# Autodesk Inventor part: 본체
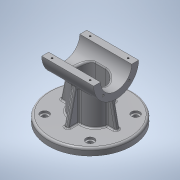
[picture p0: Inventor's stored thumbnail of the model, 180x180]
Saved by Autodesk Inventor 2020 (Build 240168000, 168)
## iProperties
Created: 2015-12
Part Number: 본체
Material: 알루미늄 6061
Document SubType Name: Modeling
Designer: mduedu
Density: 2.71 g/cm^3
Appearance: 알루미늄 - 평지
Mass: 544.569 g
Surface Area: 542.441 cm^2
Volume: 200.948 cm^3
Author: mduedu
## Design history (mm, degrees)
sketch "스케치1"
  geometry: L1 (45, 40)-(-45, 40); L2 (-45, 40)-(-45, -40); L3 (-45, -40)-(45, -40); L4 (45, -40)-(45, 40); L5 (45, 40)-(-45, -40); L6 (-45, 40)-(45, -40); 2 further points
  constraints: 12 end point, 2 midpoint, 2 parallel, 1 coincident, 1 horizontal, 1 perpendicular, 3 other
  dimensions: "d0" = 90 distance of L2.end L3.end; "d2" = 80 distance of L1.end L2.end
extrude "돌출1" new body sketch "스케치1" distance "d3" = 10; taper "d4" = 0 deg
sketch "스케치2"
  geometry: C1 r 32.5 at (80, 0); 1 further point
  constraints: 1 centre point
  dimensions: "d5" = 65 diameter of C1; "d116" = 80 distance of point (0, 0) C1.centre
extrude "돌출2" join sketch "스케치2" stored distance "d7" = 75; taper "d8" = 0 deg
sketch "스케치3"
  geometry: L1 (-27.5, -20)-(27.5, -20); L2 (27.5, -20)-(27.5, 20); L3 (27.5, 20)-(-27.5, 20); L4 (-27.5, 20)-(-27.5, -20); L5 (-27.5, -20)-(27.5, 20); L6 (27.5, -20)-(-27.5, 20); 1 further point
  constraints: 12 end point, 2 midpoint, 2 parallel, 1 horizontal, 1 perpendicular
  dimensions: "d9" = 55 distance of L2.end L3.end; "d11" = 40 distance of L1.end L2.end
extrude "돌출3" new body sketch "스케치3" stored distance "d12" = 75; taper "d13" = 0 deg
fillet "모깎기1"
fillet "모깎기2"
feature "결합1"
  node "솔리드2"
sketch "스케치4"
  geometry: L1 (-37.5, 47.5)-(37.5, 47.5) reference; L2 (32.5, 47.5)-(40.208, 10); L3 (37.5, 47.5)-(37.5, 112.5) reference; L4 (60.208, 0)-(60.208, 10) reference; L5 (60.208, 10)-(-60.208, 10) reference; 1 further point
  constraints: 2 end point, 2 point on line
  dimensions: "d15" = 5 distance from line of L2.start L3; "d117" = 20 distance from line of L2.end L4
sketch "스케치5"
  geometry: L1 (10, 35.208)-(58.179, 24.085); L2 (0, 60.208)-(10, 60.208) reference; L3 (10, -60.208)-(10, 60.208) reference; 2 further points
  constraints: 2 end point, 1 point on line, 2 other
  dimensions: "d118" = 25 distance from line of L1.start L2; "d119" = 77 deg angle of L1 L3
feature "리브1" dims "d19" = 1, "d20" = 6, "d21" = 0, "d22" = 0, "d23" = 1, "d24" = 1
feature "리브2" dims "d25" = 1, "d26" = 6, "d27" = 0, "d28" = 0, "d29" = 1, "d30" = 1
fillet "모깎기4" dims "d31" = 2
fillet "모깎기5" dims "d32" = 2
fillet "모깎기16" dims "d149" = 2
sketch "스케치6"
  geometry: L1 (0, 0)-(-32.88, 32.88); L2 (0, 0)-(-46.5, 0); A1 r 46.5 centre (0, 0) between (-32.88, 32.88) and (-46.5, 0); 5 further points
  constraints: 4 end point, 2 coincident, 2 point on circle, 1 centre point, 1 horizontal, 5 other
  dimensions: "d120" = 93 diameter of A1; "d122" = 45 deg angle of L1 L2; "d126" = 360 deg dimension on point (0, 0) point (-32.88, 32.88) (derived)
hole "구멍1" sketch "스케치6" at (-32.88, 32.88), (-32.88, -32.88), (32.88, -32.88), (32.88, 32.88) diameter "d34" = 7; stored, may be unused: countersink angle "d38" = 90 deg, drill point angle "d40" = 118 deg; dims "d35" = 6, "d36" = 12, "d37" = 3, "d39" = 8
fillet "모깎기13" dims "d131" = 3
hole "구멍2" diameter "d44" = 45; stored, may be unused: countersink angle "d48" = 90 deg, drill point angle "d50" = 118 deg; dims "d42" = 10, "d43" = 10, "d45" = 6, "d46" = 4, "d47" = 2, "d49" = 8
sketch "스케치7" dims "d52" = 26.5
  geometry: L1 (0, 0)-(32.5, 0); L2 (0, 0)-(22.981, 22.981); A1 r 32.5 centre (0, 0) between (32.5, 0) and (22.981, 22.981) reference; 3 further points
  constraints: 4 end point, 2 point on circle, 1 coincident, 1 horizontal, 1 point on line, 3 other
  dimensions: "d51" = 45 deg angle of L2 L1
hole "구멍3" sketch "스케치7" at (18.738, 18.738) diameter "d54" = 3.242; stored, may be unused: countersink angle "d58" = 90 deg, drill point angle "d60" = 118 deg; dims "d55" = 8, "d56" = 4, "d57" = 2, "d59" = 10
sketch "스케치9"
  geometry: L1 (-75, 82.5)-(75, 82.5); L2 (75, 82.5)-(75, 0); L3 (75, 0)-(-75, 0); L4 (-75, 0)-(-75, 82.5); C1 r 32.5 at (0, 0) reference; 2 further points
  constraints: 8 end point, 2 parallel, 1 coincident, 1 horizontal, 1 midpoint, 1 perpendicular
  dimensions: "d71" = 50 distance edge to line of C1 L1; "d148" = 150 distance of L1.start L1.end
extrude "돌출5" cut sketch "스케치9" extent not by distance; stored distance "d73" = 0; taper "d74" = 0 deg
node "작업 평면1"
sketch "스케치10"
  geometry: L1 (-7.5, 15)-(7.5, 15); L2 (-7.5, -15)-(7.5, -15); A1 r 15 centre (-7.5, 0) between (-7.5, 15) and (-7.5, -15); A2 r 15 centre (7.5, 0) between (7.5, -15) and (7.5, 15); A3 r 20 centre (-7.5, 0) between (-7.5, 20) and (-26.977, 4.545) reference; A4 r 20 centre (7.5, 0) between (26.977, 4.545) and (7.5, 20) reference; 1 further point
  constraints: 7 point on circle, 4 end point, 4 tangent, 3 point on line, 2 centre point, 2 horizontal, 1 concentric
  dimensions: "d150" = 5 radial gap between concentric circles of A1 A3; "d151" = 5 radial gap between concentric circles of A2 A4
extrude "돌출6" cut sketch "스케치10" extent not by distance; stored distance "d78" = 50; taper "d79" = 0 deg
fillet "모깎기10" dims "d80" = 3
sketch "스케치11"
  geometry: 2 further points
  constraints: 1 coincident
hole "구멍4" sketch "스케치11" at (0, 0) diameter "d81" = 11; stored, may be unused: countersink angle "d85" = 90 deg, drill point angle "d87" = 118 deg; dims "d82" = 8, "d83" = 42, "d84" = 10, "d86" = 10
sketch "스케치12"
  geometry: C1 r 12 at (0, 0); 1 further point
  constraints: 1 centre point, 1 coincident
  dimensions: "d88" = 24 diameter of C1
extrude "돌출7" cut sketch "스케치12" extent not by distance; stored distance "d89" = 5; taper "d90" = 0 deg
fillet "모깎기11" dims "d94" = 0.5
node "작업 평면3"
sketch "스케치17"
  geometry: 2 further points
  constraints: 1 horizontal alignment, 1 other
  dimensions: "d154" = 3.5 distance of point (-3.5, 0) point (0, 0)
feature "엠보싱1" sketch "스케치17" dims "d155" = 0.5, "d156" = 0
sketch "스케치18"
  geometry: L1 (-75, 0)-(-75, 10) reference; L2 (0, 0)-(-75, 0) reference; 2 further points
  dimensions: "d157" = 10 distance from line of point (-65, 5) L1; "d158" = 5 distance from line of point (-65, 5) L2
hole "구멍8" sketch "스케치18" at (-65, 5) diameter "d159" = 2.487; stored, may be unused: countersink angle "d163" = 90 deg, drill point angle "d165" = 118 deg; dims "d160" = 8, "d161" = 4, "d162" = 2, "d164" = 10
chamfer "모따기2" distance "d173" = 1; stored, may be unused: second distance "d174" = 2, angle "d175" = 45 deg
sketch "스케치19"
  geometry: C1 r 1.7 at (0, 15) reference; C2 r 1.7 at (15, 0) reference; C3 r 1.7 at (-15, 0) reference; C4 r 1.7 at (0, -15) reference; 1 further point
hole "구멍9" sketch "스케치19" at (0, 15), (-15, 0), (0, -15), (15, 0) diameter "d176" = 2.459; stored, may be unused: countersink angle "d180" = 90 deg, drill point angle "d182" = 118 deg; dims "d177" = 6, "d178" = 4, "d179" = 2, "d181" = 8
node "솔리드1"
mirror "대칭1"
mirror "대칭2"
pattern_circular "원형 패턴1" dims angle "d62" = 360 deg
mirror "대칭3"
pattern_linear "직사각형 패턴1" dims "d168" = 55, "d171" = 55
node "참조1"
node "참조2"
node "참조3"
node "참조4"
